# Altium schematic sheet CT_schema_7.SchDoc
size 278 x 170 mm
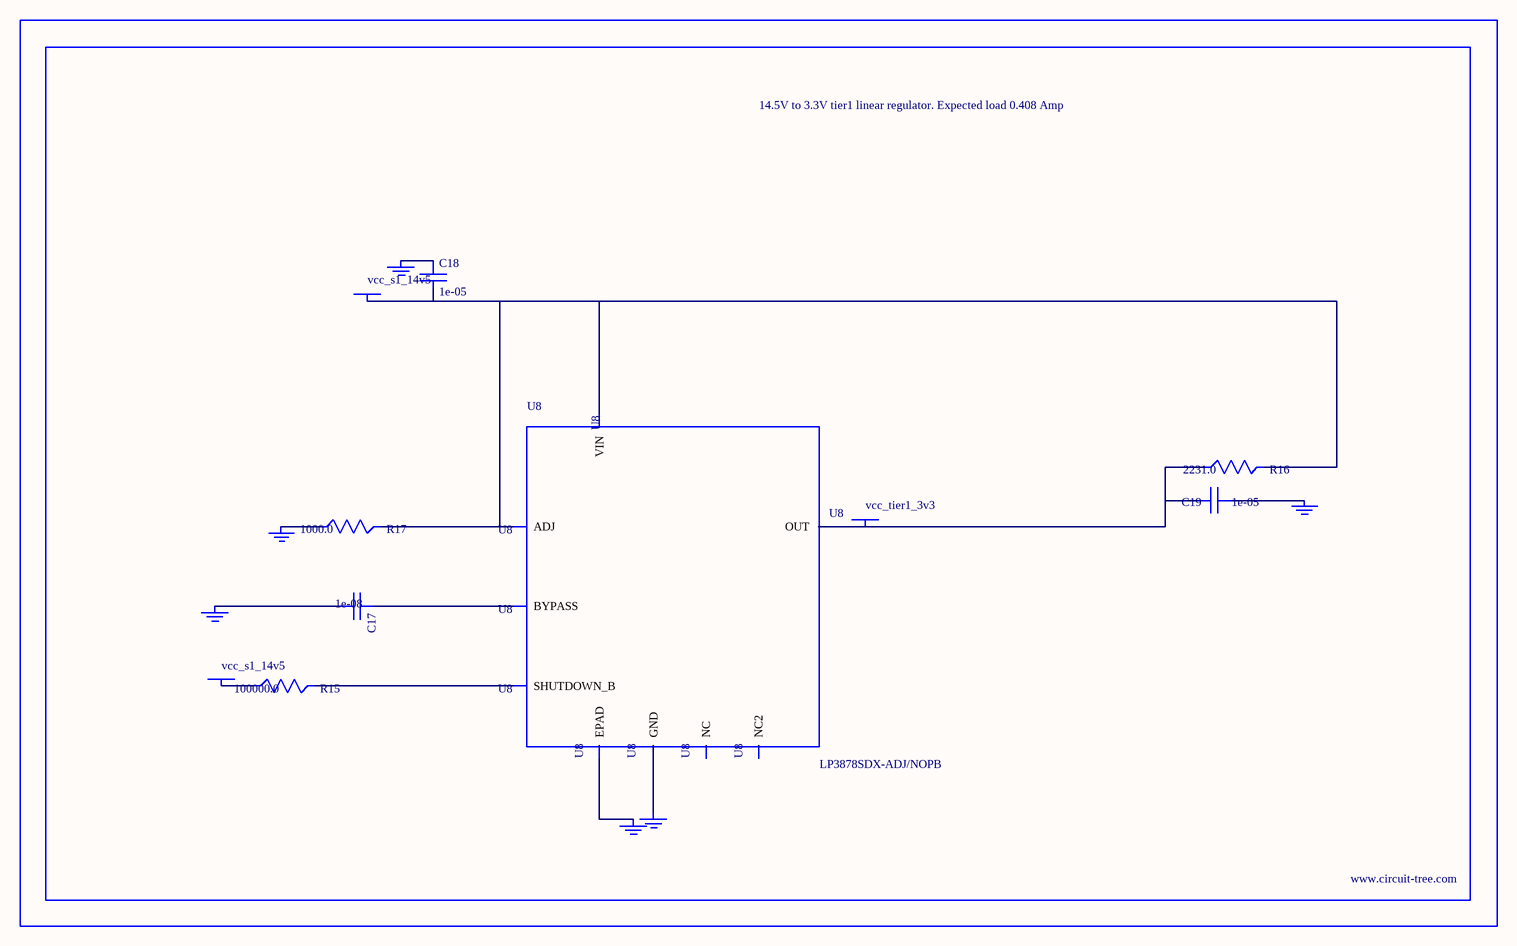
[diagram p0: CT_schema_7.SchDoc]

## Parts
BORDER6  (no value)
C17  1e-08  [C0402]
C18  1e-05  [C1210]
C19  1e-05  [C1210]
GND_INSTANCE_6_0  (no value)
GND_INSTANCE_6_1  (no value)
GND_INSTANCE_6_2  (no value)
GND_INSTANCE_6_3  (no value)
GND_INSTANCE_6_4  (no value)
GND_INSTANCE_6_5  (no value)
POWER_INSTANCE_6_0  vcc_s1_14v5
POWER_INSTANCE_6_1  vcc_s1_14v5
POWER_INSTANCE_6_2  vcc_tier1_3v3
R15  100000.0  [R0603]
R16  2231.0  [R0603]
R17  1000.0  [R0603]
U8  LP3878SDX-ADJ/NOPB  [WSON-8]

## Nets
NetC17_1: C17.1 U8.1(BYPASS)
NetC17_2: C17.2 GND_INSTANCE_6_0.0(GND)
NetC18_1: C18.1 GND_INSTANCE_6_1.0(GND)
NetC18_2: C18.2 POWER_INSTANCE_6_0.0(PWR) R16.2 R17.2 U8.4(VIN) U8.6(ADJ)
NetC19_1: C19.1 GND_INSTANCE_6_2.0(GND)
NetC19_2: C19.2 POWER_INSTANCE_6_2.0(PWR) R16.1 U8.5(OUT)
NetGND_INSTANCE_6_3_0: GND_INSTANCE_6_3.0(GND) R17.1
NetGND_INSTANCE_6_4_0: GND_INSTANCE_6_4.0(GND) U8.PAD(EPAD)
NetGND_INSTANCE_6_5_0: GND_INSTANCE_6_5.0(GND) U8.3(GND)
NetPOWER_INSTANCE_6_1_0: POWER_INSTANCE_6_1.0(PWR) R15.1
NetR15_2: R15.2 U8.8(SHUTDOWN_B)

Not connected (* = marked no-connect by the designer): U8 2(NC) 7(NC2)

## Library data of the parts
BORDER6 = BORDER_PAGE6
C17 = C0402C103K3RAC
C18 = C1210C106K5PACTU
C19 = GRM32DR61E106MA12L
GND_INSTANCE_6_0-GND_INSTANCE_6_5 = GND
POWER_INSTANCE_6_0-POWER_INSTANCE_6_2 = PWR
R15 = RC0603JR-07100KL
R16 = R16
R17 = RC0603JR-071KL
